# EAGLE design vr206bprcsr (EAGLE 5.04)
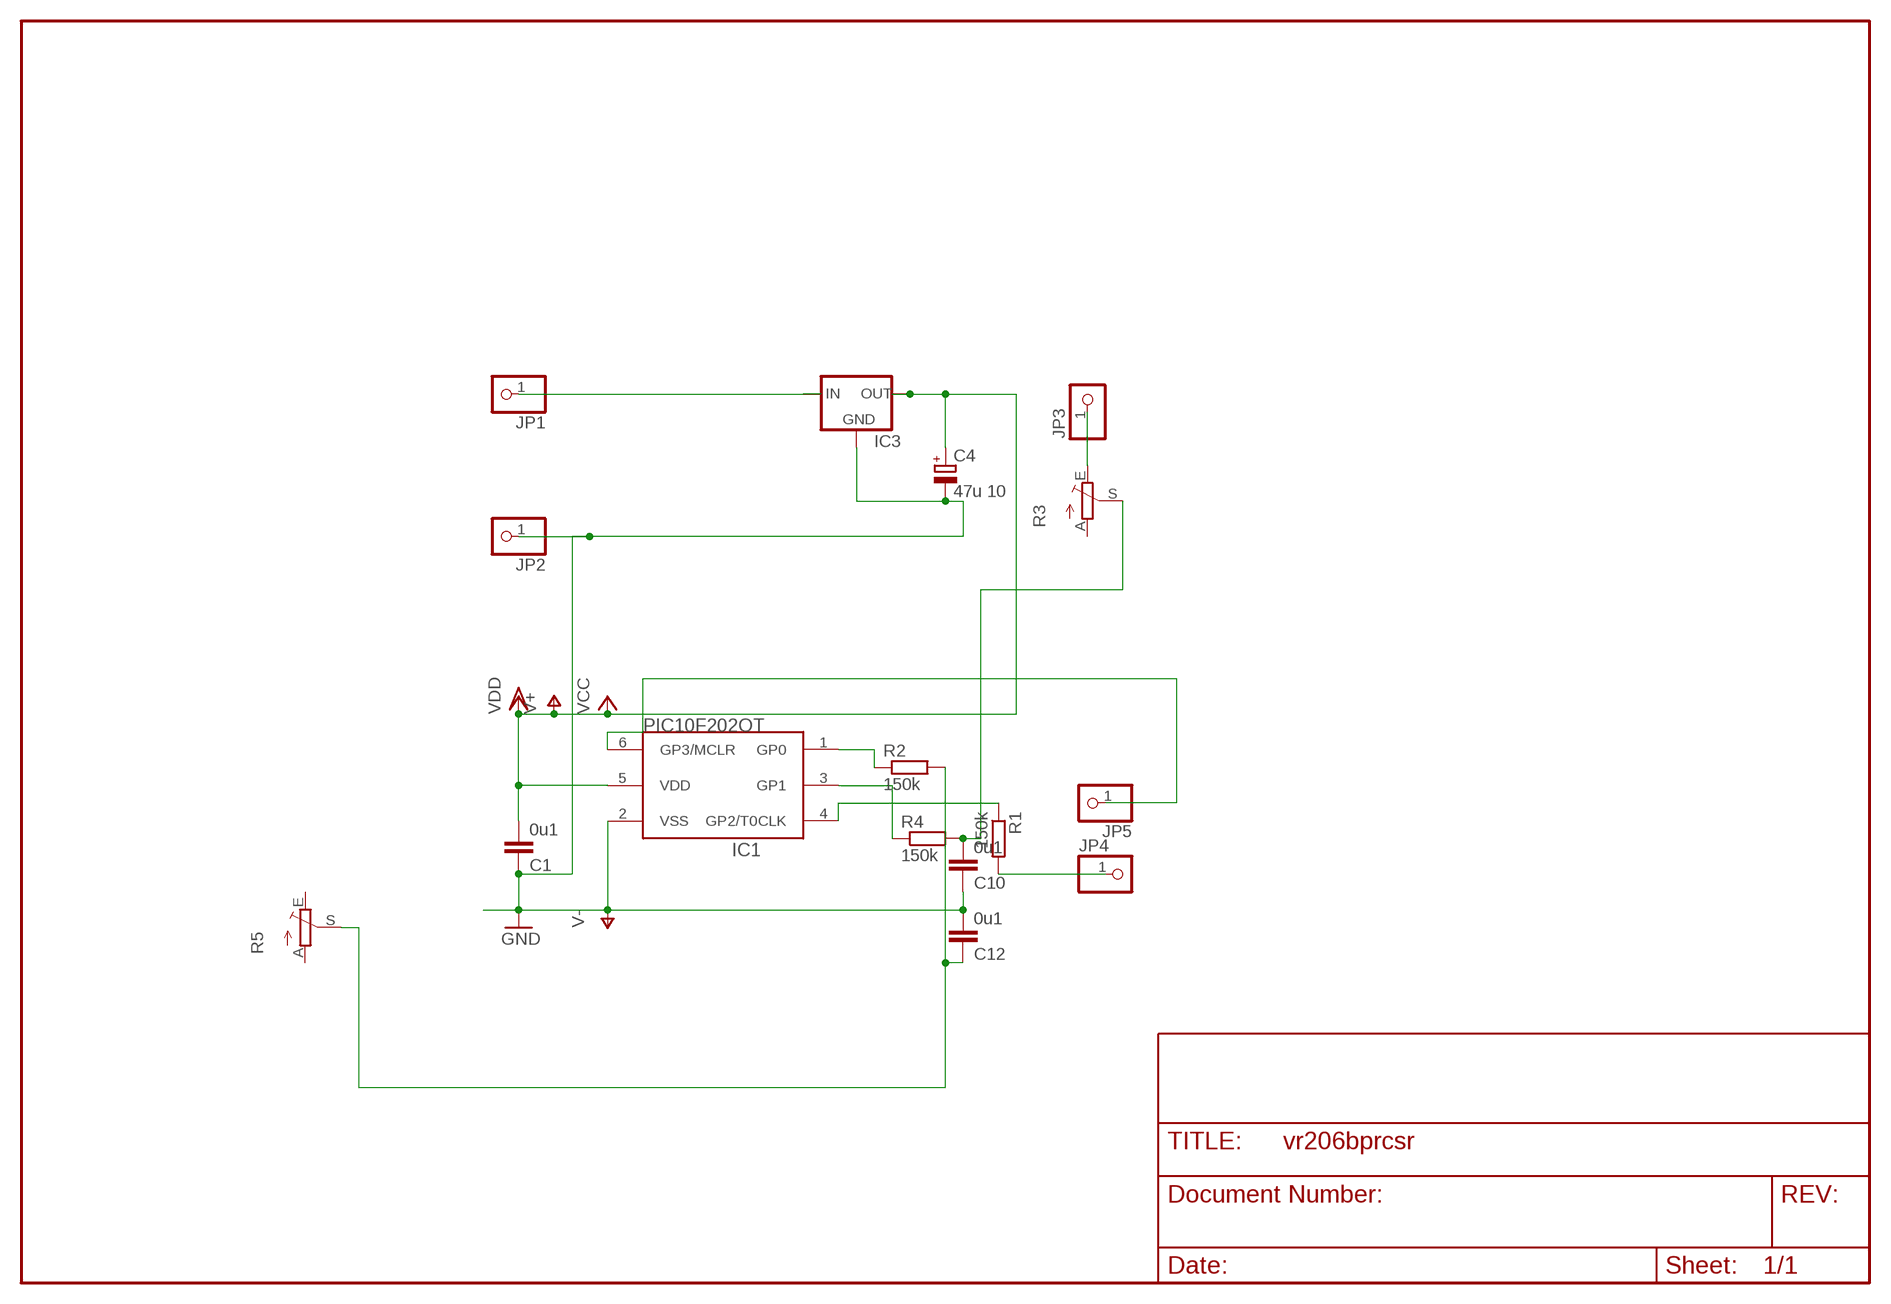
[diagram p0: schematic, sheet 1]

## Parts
C1  0u1  C-EUC1206  [C1206]
C4  47u 10  CPOL-EUE2.5-6  [E2,5-6]
C10  0u1  C-EUC1206  [C1206]
C12  0u1  C-EUC1206  [C1206]
IC1  PIC10F202OT  [SOT23-6]
IC3  78LXX  [78LXX]
JP1  PINHD-1X1  [1X01]
JP2  PINHD-1X1  [1X01]
JP3  PINHD-1X1  [1X01]
JP4  PINHD-1X1  [1X01]
JP5  PINHD-1X1  [1X01]
R1  150k  R-EU_R0805  [R0805]
R2  150k  R-EU_R1206  [R1206]
R3  TRIM_EU-CA6V  [CA6V]
R4  150k  R-EU_R1206  [R1206]
R5  TRIM_EU-CA6V  [CA6V]

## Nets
N$1: JP3.1 R3.E
N$2: JP4.1 R1.2
N$3: IC1.6(GP3/MCLR) JP5.1
N$4: IC1.1(GP0) R2.1
N$5: IC1.4(GP2/T0CLK) R1.1
N$7: IC1.3(GP1) R4.1
N$12: C10.2 R3.S R4.2
N$13: C12.1 R2.2 R5.S
N$20: IC3.IN JP1.1
V+: C1.2 C4.+ IC1.5(VDD) IC3.OUT ; supply symbol labelled VCC, VDD
V-: C1.1 C4.- C10.1 C12.2 IC1.2(VSS) IC3.GND JP2.1 ; supply symbol labelled GND
Unconnected: R3.A R5.A R5.E

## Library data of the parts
C1 C10 C12 = rcl:C-EU: CAPACITOR, European symbol
C4 = rcl:CPOL-EU: POLARIZED CAPACITOR, European symbol
IC1 = microchip-5:PIC10F20*: uPC nW 0,25/0,5k Program Flash memory
IC3 = v-reg:78LXX: VOLTAGE REGULATOR
JP1-JP5 = pinhead:PINHD-1X1: PIN HEADER
R1 R2 R4 = rcl:R-EU_: RESISTOR, European symbol
R3 R5 = pot:TRIM_EU-: POTENTIOMETER

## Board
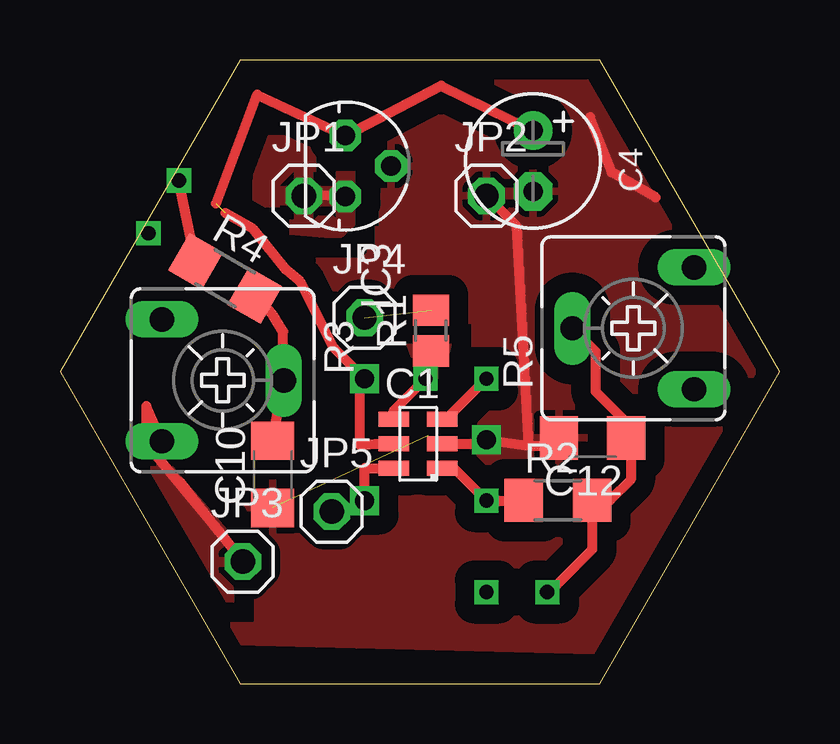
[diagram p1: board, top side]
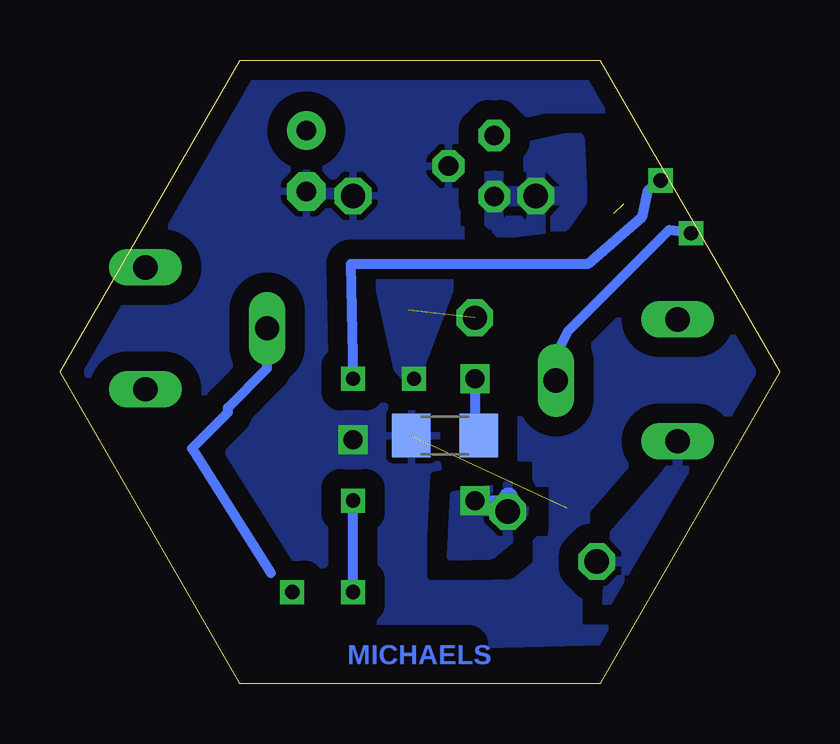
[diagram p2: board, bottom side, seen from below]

Size 30 x 25.98 mm. Coordinates in mm from the lower left corner, seen from the top.
Outline: 7.5,0 22.5,0 30,12.99 22.5,25.98 7.5,25.98 0,12.99 7.5,0
Copper layers (1*16): Top 0.035mm / dielectric 1.5mm / Bottom 0.035mm
Design rules "default *": minimum track width 10mil, minimum drill 24mil, track to track 8mil, track to pad 8mil, pad to pad 8mil, via to via 8mil, smd to smd 8mil, copper to edge 10mil, drill to drill 8mil, minimum pad ring 10mil, minimum via ring 8mil, stop-mask expansion 4mil, vias tented up to drill 0mil, thermal gap 10mil

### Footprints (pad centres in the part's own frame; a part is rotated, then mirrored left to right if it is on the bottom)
C1206 = smd 1.6 x 1.8: 1 -1.4,0; 2 1.4,0
E2,5-6 = drill 0.813 pad 1.6 round: + -1.27,0 | drill 0.813 pad 1.6 octagon: - 1.27,0
SOT23-6 = smd 0.635 x 1.27: 1 -1.016,-1.016; 2 0,-1.016; 3 1.016,-1.016; 4 1.016,1.016; 5 0,1.016; 6 -1.016,1.016
78LXX = drill 0.813 octagon: GND 0,1.905; IN 1.27,0; OUT -1.27,0
1X01 = drill 1.016 octagon: 1 0,0
R0805 = smd 1.3 x 1.5: 1 -0.85,0; 2 0.85,0
R1206 = smd 1.6 x 1.803: 1 -1.422,0; 2 1.422,0
CA6V = drill 1.016 long: A -2.54,-2.54; E 2.54,-2.54; S 0,2.54

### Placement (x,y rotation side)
C1  13.95,10.33 0 bottom
C4  19.72,21.77 270 top
C10  8.87,8.71 90 top
C12  22.2,10.23 180 top
IC1  14.93,9.99 90 top
IC3  11.9,21.56 270 top
JP1  10.16,20.32 0 top
JP2  17.78,20.32 0 top
JP3  7.62,5.08 0 top
JP4  12.7,15.24 0 top
JP5  11.33,7.16 0 top
R1  15.46,14.71 90 top
R2  20.76,7.63 0 top
R3  6.79,12.63 270 top
R4  6.89,16.88 330 top
R5  23.9,14.8 90 top

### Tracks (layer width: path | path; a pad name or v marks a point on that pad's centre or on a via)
N$1
  Top 0.406: 6.63,6.33 5,8.4 | 6.63,6.33 JP3.1 | R3.E 3.6,11.56 3.6,10 6.63,6.33
  pour Top (isolate 0.61): 2,12.2 7.1,3.5 6.8,6.3 4.9,8.5
  pour Bottom (isolate 0.61): 2.1,12.1 7.2,3.4 6.9,6.2 5,8.4
N$2  (1 unrouted)
N$3  (via drill 0.8)
  Top 0.406: IC1.6 12.7,8.97 v12.7,7.62
  Bottom 0.406: 11.3,7.59 JP5.1 11.33,7.62 v12.7,7.62
  Bottom 0.813: 11.3,7.59 11.3,7.76
  pour Bottom (isolate 0.61): 10.5,8.37 13.55,7.81 13.68,5.31 12.06,5.37 10.75,6.43
N$4  (via drill 0.6)
  Top 0.406: IC1.1 16.43,8.97 v17.78,7.62 19.32,7.62 R2.1
  Bottom 0.406: v17.78,7.62 17.78,3.72 17.8,3.7
N$5  (via drill 0.6)
  Top 0.406: IC1.4 13.91,11.37 v15.24,12.7 15.24,13.97 15.49,13.72 15.49,13.5 R1.1
  pour Bottom (isolate 0.406): 15.3,12.66 13.7,16.9 15.2,17.1 16.6,16.7 15.8,13.16
  pour Top (isolate 0.406): 15.3,12.66 13.7,16.9 15.5,17.5 16.6,16.7 15.8,13.16
N$7  (via drill 0.6)
  Top 0.406: IC1.3 16.09,11.01 v17.78,12.7 | R4.1 v4.96,20.96
  Bottom 0.406: v17.78,12.7 17.88,17.48 7.99,17.48 5.75,19.42 5.51,20.52 v4.96,20.96
N$8  (via drill 0.6)
  other vias: 17.78,3.81
N$9  (via drill 0.6)
  other vias: 20.32,3.81
N$10  (via drill 0.6)
  other vias: 4.96,20.96
N$11  (via drill 0.6)
  other vias: 3.69,18.76
N$12
  Top 0.406: R4.2 8.88,15.34 9.31,14.66 9.31,13.62 R3.S C10.2
  Bottom 0.406: R3.S 9.23,13.87 8.8,14.7 4.6,18.9 3.7,18.8
N$13
  Top 0.406: 20.4,3.8 22.18,5.58 R2.2 22.93,7.63 23.8,8.5 23.8,10.04 | 23.8,10.04 C12.1 | 23.8,10.04 23.8,10.7 22.33,12.17 22.33,13.84 R5.S
  Bottom 0.406: R5.S 21.36,13.13 23,11.5 23,11.3 24.5,9.8 21.2,4.6
N$20
  Top 0.406: IC3.IN 10.1,20.38 JP1.1
  pour Top (isolate 0.813): 8.51,22.61 8.41,20.28 9.36,19.12 11.56,18.92 12.06,19.43 12.06,21.34 11.43,21.97
  pour Bottom (isolate 0.813): 8.51,22.61 8.41,20.18 9.06,19.22 11.56,18.92 12.06,19.43 12.06,21.34 11.43,21.97
V+  (via drill 0.8)  (1 unrouted)
  Top 0.406: C4.+ 15.89,24.91 IC3.OUT 8.22,24.54 6.5,20 | IC1.5 13.14,9.99 12.5,9.93 12.5,12.7 v12.7,12.7 11.43,13.97 10.03,16.74 9.45,17.22 8.05,18.95 6.9,19.6
  Bottom 0.406: C1.2 12.7,10.33 v12.7,12.7
V-  (via drill 0.8)  (1 unrouted)
  Top 0.406: 24.84,20.26 23,21.3 22.1,23.6 | IC1.2 17.55,9.99 v17.78,10.16 19.56,9.91 | 19.56,9.91 19.05,19.05 JP2.1 | 19.56,9.91 20.48,9.91 C12.2
  pour Top (isolate 0.813, rank 4): 12.24,25.35 15.23,28.55 24.4,28.18 25.15,22.48 26.18,23.21 28.48,20.56 31.06,15.58 23.09,1.35 7.34,1.75 -0.28,14.57 3.92,22.34 6.61,27.24
  pour Bottom (isolate 0.813, rank 4): 12.24,25.35 15.23,28.55 24.4,28.18 25.15,22.48 26.18,23.21 28.48,20.56 31.06,15.58 23.09,1.35 7.34,1.75 -0.28,14.57 4.82,23.74 7.51,28.64

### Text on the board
Bottom: MICHAELS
